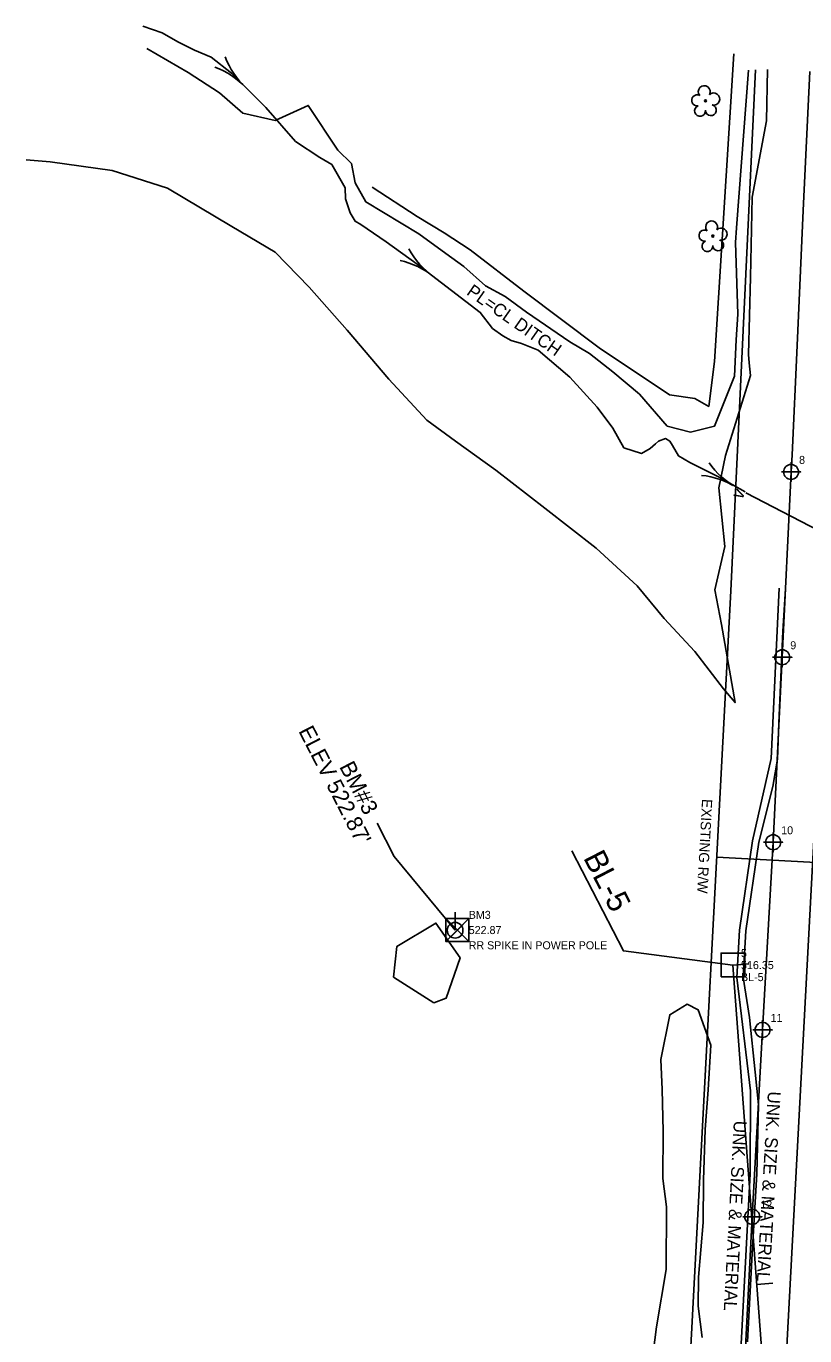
# Model space of a CAD drawing. Extents: x 1534145 to 1537876, y 509021 to 513201.
# Drawn here: x 1535793.4 to 1536036.7, y 512378.3 to 512787.3 of the extents above; entities that cross this region are included whole.
import ezdxf

# ---------------------------------------------------------------- set-up
doc = ezdxf.new("R2010")
doc.units = 0
for name, color, linetype in [('CTL Bench Mark CELL', 7, 'Continuous'), ('CTL Bench Mark Cogo Comment', 7, 'Continuous'), ('CTL Bench Mark Cogo Elevation', 7, 'Continuous'), ('CTL Bench Mark Cogo Number', 7, 'Continuous'), ('CTL Bench Mark Leader', 7, 'Continuous'), ('CTL Bench Mark Text', 7, 'Continuous'), ('CTL Supplemental Horizontal and Vertical CELL', 7, 'Continuous'), ('CTL Supplemental Horizontal and Vertical Cogo Comment', 7, 'Continuous'), ('CTL Supplemental Horizontal and Vertical Cogo Elevation', 7, 'Continuous'), ('CTL Supplemental Horizontal and Vertical Cogo Number', 7, 'Continuous'), ('Exist Horizontal Alignment', 7, 'Continuous'), ('Exist Horizontal Baseline Alignment', 7, 'Continuous'), ('Exist Horizontal Baseline Alignment Station Label', 7, 'Continuous'), ('Exist Horizontal Baseline Alignment Tick small', 7, 'Continuous'), ('Exist Hydro Stream Flow Arrow CELL', 7, 'Continuous'), ('Exist Hydro Stream or Body of Water', 7, 'Continuous'), ('Exist Other Culture Fence Line', 7, 'Continuous'), ('Exist Property Line Text', 7, 'Continuous'), ('Exist Right of Way Line', 7, 'Continuous'), ('Exist Right of Way Line Text', 7, 'Continuous'), ('Exist Right of Way Width CELL', 7, 'Continuous'), ('Exist Roads EOP', 7, 'Continuous'), ('Exist Roads EOP Cogo Number', 7, 'Continuous'), ('Exist Roads EOP Cogo Point CELL', 7, 'Continuous'), ('Exist Structure Minor Culvert Topo', 7, 'Continuous'), ('Exist Structure Minor Culvert Topo Terminator', 7, 'Continuous'), ('Exist Utilities Power Pole CELL', 7, 'Continuous'), ('Exist Utilities Telephone UG Cable', 7, 'Continuous'), ('Exist Utilities Telephone UG Cable Text', 7, 'Continuous'), ('Exist Utilities Telephone UG FO SUE', 7, 'Continuous'), ('Exist Utilities Telephone UG FO SUE Text', 7, 'Continuous'), ('Exist Vegetation Hedge Row', 7, 'Continuous'), ('Exist Vegetation Tree CELL', 7, 'Continuous'), ('Exist Vegetation Woods Line', 7, 'Continuous')]:
    doc.layers.add(name, color=color, linetype=linetype)

# ---------------------------------------------------------------- blocks, each defined once
blk = doc.blocks.new('EXIST UTILITIES POWER POLE')
at = {"layer": 'Exist Utilities Power Pole CELL'}
for q in [(0, 0.1125), (0, 0)]:
    blk.add_line((0, 0), q, dxfattribs=at)
blk.add_circle((0, 0), 0.049, dxfattribs=at)
blk = doc.blocks.new('CTL SUPPLEMENTAL HORIZONTAL AND VERTICAL')
at = {"layer": 'CTL Supplemental Horizontal and Vertical CELL'}
blk.add_line((0, 0), (0, 0), dxfattribs=at)
blk.add_lwpolyline([(-0.1043, 0.0004), (0.0005, 0.1052), (0.1055, 0.0002), (0.0007, -0.1047)], close=True, dxfattribs=at)
blk = doc.blocks.new('CTL BENCH MARK')
at = {"layer": 'CTL Bench Mark CELL'}
blk.add_line((0, 0), (0, 0), dxfattribs=at)
blk.add_lwpolyline([(-0.072, 0.07175), (0.07175, 0.07175), (0.07175, -0.072), (-0.072, -0.072)], close=True, dxfattribs=at)
for points in [[(0.07175, 0.07175), (-0.072, -0.072), (-0.000125, -0.000125), (0.07175, -0.072), (-0.072, 0.07175)], [(-0.000125, -0.000125), (0.07175, 0.07175), (-0.072, 0.07175), (-0.000125, -0.000125)], [(-0.000125, -0.000125), (-0.072, -0.072), (0.07175, -0.072), (-0.000125, -0.000125)]]:
    blk.add_lwpolyline(points, dxfattribs=at)

msp = doc.modelspace()

# ---------------------------------------------------------------- linework, layer by layer
at = {"layer": 'CTL Bench Mark Leader'}
msp.add_lwpolyline([(1535927.46, 512504.93), (1535908.43, 512527.94), (1535903.05, 512538.38)], dxfattribs=at)
at = {"layer": 'Exist Horizontal Alignment'}
msp.add_line((1536043.59, 512609.44), (1536025.64, 512271.8), dxfattribs=at)
at = {"layer": 'Exist Horizontal Baseline Alignment'}
msp.add_line((1536014.28, 512494.06), (1536066.28, 511797.6), dxfattribs=at)
at = {"layer": 'Exist Horizontal Baseline Alignment Station Label'}
msp.add_lwpolyline([(1535963.95, 512529.74), (1535980.06, 512498.5), (1536014.28, 512494.06)], dxfattribs=at)
at = {"layer": 'Exist Horizontal Baseline Alignment Tick small'}
for p, q in [((1536014.28, 512494.06), (1536019.27, 512494.43)), ((1536021.72, 512394.34), (1536026.71, 512394.71))]:
    msp.add_line(p, q, dxfattribs=at)
at = {"layer": 'Exist Hydro Stream Flow Arrow CELL'}
for p, q in [((1535857.53, 512772.63), (1535857.53, 512772.63)), ((1535915.6, 512712.96), (1535915.6, 512712.96)), ((1536009.95, 512646.45), (1536009.95, 512646.45))]:
    msp.add_line(p, q, dxfattribs=at)
for points in [[(1535855.58, 512777.77), (1535856.11, 512776.4), (1535856.8, 512775.07), (1535857.5, 512773.77), (1535858.28, 512772.55), (1535859.16, 512771.36), (1535860.1, 512770.2), (1535861.09, 512769.11)], [(1535852.37, 512774.52), (1535853.74, 512774), (1535855.08, 512773.33), (1535856.39, 512772.65), (1535857.61, 512771.88), (1535858.82, 512771.02), (1535859.99, 512770.09), (1535861.09, 512769.11)], [(1535912.99, 512717.8), (1535913.7, 512716.52), (1535914.56, 512715.29), (1535915.42, 512714.09), (1535916.36, 512712.99), (1535917.38, 512711.92), (1535918.47, 512710.89), (1535919.6, 512709.95)], [(1535910.24, 512714.15), (1535911.66, 512713.82), (1535913.08, 512713.33), (1535914.47, 512712.83), (1535915.79, 512712.23), (1535917.1, 512711.54), (1535918.38, 512710.77), (1535919.6, 512709.95)], [(1536006.81, 512650.96), (1536007.66, 512649.76), (1536008.65, 512648.64), (1536009.64, 512647.54), (1536010.7, 512646.56), (1536011.84, 512645.61), (1536013.04, 512644.71), (1536014.26, 512643.91)], [(1536004.48, 512647.01), (1536005.94, 512646.85), (1536007.4, 512646.53), (1536008.84, 512646.19), (1536010.22, 512645.74), (1536011.6, 512645.2), (1536012.96, 512644.58), (1536014.26, 512643.91)]]:
    msp.add_lwpolyline(points, dxfattribs=at)
at = {"layer": 'Exist Hydro Stream or Body of Water'}
msp.add_lwpolyline([(1536018.1, 512641.86), (1536009.95, 512646.45), (1536000.77, 512651.08), (1535997.2, 512653.11), (1535995.33, 512656.33), (1535994.53, 512657.73), (1535993.14, 512658.52), (1535991.04, 512657.67), (1535990.05, 512656.84), (1535988.35, 512655.38), (1535985.73, 512653.88), (1535980.22, 512655.65), (1535976.73, 512661.75), (1535971.8, 512668.31), (1535963.32, 512677.68), (1535953.37, 512686.16), (1535948.17, 512688.17), (1535945, 512689.2), (1535942.34, 512690.58), (1535939.15, 512692.86), (1535935.28, 512697.91), (1535926.3, 512704.82), (1535915.6, 512712.96), (1535905.92, 512719.99), (1535897.96, 512725.37), (1535896.22, 512726.4), (1535894.65, 512729.05), (1535893.17, 512733.35), (1535893.09, 512736.87), (1535891.02, 512740.47), (1535888.96, 512744.09), (1535885.13, 512746.3), (1535877.54, 512751.34), (1535868.26, 512761.96), (1535857.53, 512772.63), (1535851.19, 512777.67), (1535846.03, 512779.84), (1535840.84, 512782.43), (1535835.91, 512785.23), (1535829.84, 512787.32)], dxfattribs=at)
at = {"layer": 'Exist Other Culture Fence Line'}
msp.add_lwpolyline([(1535901.55, 512737.02), (1535915.61, 512727.91), (1535924.04, 512722.82), (1535932.11, 512717.42), (1535948.95, 512704.53), (1535972.5, 512686.87), (1535994.44, 512672.19), (1536002.33, 512671.02), (1536006.72, 512668.54), (1536008.5, 512682.58), (1536014.58, 512778.73)], dxfattribs=at)
at = {"layer": 'Exist Right of Way Line'}
for p, q in [((1536021.36, 512773.66), (1536013.63, 512610.95)), ((1536013.63, 512610.95), (1535995.68, 512273.4))]:
    msp.add_line(p, q, dxfattribs=at)
at = {"layer": 'Exist Right of Way Width CELL'}
msp.add_line((1536009.2, 512527.75), (1536052.92, 512525.42), dxfattribs=at)
at = {"layer": 'Exist Roads EOP'}
for points in [[(1536032.73, 512653.49), (1536034.33, 512687.61), (1536036.23, 512729.8), (1536038.31, 512773.15)], [(1536032.73, 512653.49), (1536032.43, 512648.1), (1536029.67, 512590.21), (1536026.84, 512532.42), (1536023.52, 512473.82), (1536020.32, 512415.44), (1536017.35, 512358.24), (1536017.13, 512355.26)]]:
    msp.add_lwpolyline(points, dxfattribs=at)
at = {"layer": 'Exist Roads EOP Cogo Point CELL'}
for points in [[(1536032.43, 512651.1), (1536032.43, 512645.1), (1536032.43, 512648.1), (1536035.43, 512648.1), (1536029.43, 512648.1)], [(1536029.67, 512593.21), (1536029.67, 512587.21), (1536029.67, 512590.21), (1536032.67, 512590.21), (1536026.67, 512590.21)], [(1536026.84, 512535.42), (1536026.84, 512529.42), (1536026.84, 512532.42), (1536029.84, 512532.42), (1536023.84, 512532.42)], [(1536023.52, 512476.82), (1536023.52, 512470.82), (1536023.52, 512473.82), (1536026.52, 512473.82), (1536020.52, 512473.82)], [(1536020.32, 512418.44), (1536020.32, 512412.44), (1536020.32, 512415.44), (1536023.32, 512415.44), (1536017.32, 512415.44)]]:
    msp.add_lwpolyline(points, dxfattribs=at)
for centre in [(1536032.43, 512648.1), (1536029.67, 512590.21), (1536026.84, 512532.42), (1536023.52, 512473.82), (1536020.32, 512415.44)]:
    msp.add_circle(centre, 2.34, dxfattribs=at)
at = {"layer": 'Exist Structure Minor Culvert Topo'}
msp.add_lwpolyline([(1536018.25, 512641.57), (1536072.53, 512613.43)], dxfattribs=at)
at = {"layer": 'Exist Utilities Telephone UG Cable'}
msp.add_lwpolyline([(1536028.72, 512611.84), (1536026.21, 512558.62), (1536020.37, 512532.89), (1536016.35, 512504.93), (1536015.43, 512490.16), (1536019.76, 512454.82), (1536019.68, 512428.91), (1536012.12, 512287.11), (1536007.46, 512205.21), (1536007.18, 512182.18), (1536007.51, 512112.19)], dxfattribs=at)
at = {"layer": 'Exist Utilities Telephone UG FO SUE'}
for p, q in [((1536030.72, 512611.71), (1536029.83, 512598.4)), ((1536029.83, 512598.4), (1536028.65, 512569.65)), ((1536028.65, 512569.65), (1536028.2, 512558.41)), ((1536028.2, 512558.41), (1536026.73, 512549.88)), ((1536026.73, 512549.88), (1536022.33, 512532.5)), ((1536022.33, 512532.5), (1536018.34, 512504.73)), ((1536018.34, 512504.73), (1536017.44, 512490.26)), ((1536017.44, 512490.26), (1536019.41, 512477.74)), ((1536019.41, 512477.74), (1536021.22, 512460.58)), ((1536021.22, 512460.58), (1536022.2, 512450.42)), ((1536022.2, 512450.42), (1536021.68, 512428.83)), ((1536021.68, 512428.83), (1536020.22, 512403.95)), ((1536020.22, 512403.95), (1536018.85, 512376.38))]:
    msp.add_line(p, q, dxfattribs=at)
at = {"layer": 'Exist Vegetation Hedge Row'}
msp.add_lwpolyline([(1535920.82, 512482.3), (1535908.16, 512490.31), (1535909.28, 512499.89), (1535921.44, 512507.19), (1535928.99, 512496.34), (1535924.65, 512483.72), (1535920.82, 512482.3)], dxfattribs=at)
at = {"layer": 'Exist Vegetation Tree CELL'}
for p, q in [((1536005.68, 512763.99), (1536005.68, 512763.99)), ((1536007.99, 512721.77), (1536007.99, 512721.77))]:
    msp.add_line(p, q, dxfattribs=at)
for centre in [(1536005.68, 512763.99), (1536007.99, 512721.77)]:
    msp.add_circle(centre, 0.326, dxfattribs=at)
for centre, radius, start, end in [((1536005.3, 512766.86), 1.86, 330.1651, 219.7134), ((1536003.08, 512764.15), 1.73, 62.6636, 279.3457), ((1536008.23, 512764.58), 1.9, 257.1011, 134.1999), ((1536003.98, 512760.87), 1.69, 111.5671, 6.231), ((1536007.36, 512761.09), 1.7, 181.2822, 74.56), ((1536007.6, 512724.64), 1.86, 330.1651, 219.7134), ((1536005.38, 512721.92), 1.73, 62.6636, 279.3457), ((1536010.54, 512722.36), 1.9, 257.1011, 134.1999), ((1536006.28, 512718.65), 1.69, 111.5671, 6.231), ((1536009.66, 512718.87), 1.7, 181.2822, 74.56)]:
    msp.add_arc(centre, radius, start, end, dxfattribs=at)
at = {"layer": 'Exist Vegetation Woods Line'}
for points in [[(1535831.08, 512780.4), (1535844, 512772.83), (1535853.83, 512766.49), (1535861.14, 512760.16), (1535871.19, 512757.9), (1535881.58, 512762.59), (1535890.83, 512748.57), (1535895.09, 512744.42), (1535896.27, 512738.37), (1535899.57, 512732.42), (1535916.15, 512722.43), (1535924.54, 512716.37), (1535930.2, 512712.22), (1535936.91, 512706.22), (1535943.1, 512702.9), (1535949.8, 512698.01), (1535963.31, 512688.73), (1535969.45, 512685.05), (1535976.69, 512679.41), (1535985.03, 512672.42), (1535993.74, 512662.44), (1536001.05, 512660.56), (1536008.51, 512662.41), (1536014.77, 512677.98), (1536015.25, 512689.33), (1536015.75, 512697.4), (1536015.06, 512719.76), (1536015.35, 512724.33), (1536019.14, 512773.55)], [(1536025.08, 512773.81), (1536024.74, 512757.76), (1536020.22, 512733.9), (1536019.74, 512708.9), (1536019.09, 512684.76), (1536019.32, 512682.14), (1536019.78, 512678.18), (1536011.95, 512653.25), (1536009.83, 512643.1), (1536011.76, 512624.78), (1536008.63, 512611.28), (1536010.67, 512600.43), (1536014.92, 512576.04), (1536011.29, 512580.31), (1536002.36, 512591.98), (1535992.75, 512602.37), (1535984.38, 512612.52), (1535971.52, 512624.27), (1535955.5, 512636.73), (1535940.18, 512648.63), (1535927.54, 512657.68), (1535918.6, 512664.26), (1535906.7, 512677.05), (1535893.77, 512692.42), (1535881.82, 512705.85), (1535871.2, 512716.79), (1535857.73, 512724.78), (1535837.57, 512736.77), (1535820.31, 512742.3), (1535800.9, 512745), (1535793.42, 512745.53)], [(1536004.61, 512377.71), (1536003.37, 512387.56), (1536003.49, 512396.6), (1536004.99, 512413.67), (1536005.1, 512426.91), (1536005.6, 512442.71), (1536006.5, 512455.13), (1536007.4, 512469.07), (1536003.41, 512480.12), (1535999.92, 512481.84), (1535994.51, 512478.54), (1535991.74, 512464.62), (1535992.18, 512455.19), (1535992.48, 512442.24), (1535992.34, 512427.38), (1535993.51, 512418.57), (1535993.39, 512398.99), (1535990.38, 512381.04), (1535989.37, 512372.96)]]:
    msp.add_lwpolyline(points, dxfattribs=at)

# ---------------------------------------------------------------- block references
at = {"layer": 'CTL Bench Mark CELL', "xscale": 50, "yscale": 50}
msp.add_blockref('CTL BENCH MARK', (1535928.2, 512505), dxfattribs=at)
at = {"layer": 'CTL Supplemental Horizontal and Vertical CELL', "xscale": 50, "yscale": 49.99999999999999, "rotation": 44.99999999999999}
msp.add_blockref('CTL SUPPLEMENTAL HORIZONTAL AND VERTICAL', (1536014.28, 512494.06), dxfattribs=at)
at = {"layer": 'Exist Utilities Power Pole CELL', "xscale": 50, "yscale": 50}
msp.add_blockref('EXIST UTILITIES POWER POLE', (1535927.46, 512504.93), dxfattribs=at)

# ---------------------------------------------------------------- texts
at = {"layer": 'CTL Bench Mark Cogo Comment'}
msp.add_text('RR SPIKE IN POWER POLE', height=2.5, dxfattribs=at).set_placement((1535931.7, 512499))
at = {"layer": 'CTL Bench Mark Cogo Elevation'}
msp.add_text('522.87', height=2.5, dxfattribs=at).set_placement((1535931.7, 512503.75))
at = {"layer": 'CTL Bench Mark Cogo Number'}
msp.add_text('BM3', height=2.5, dxfattribs=at).set_placement((1535931.7, 512508.5))
at = {"layer": 'CTL Bench Mark Text'}
for s, p in [("ELEV 522.87'", (1535878.38, 512567.19)), ('BM#3', (1535891.16, 512556.07))]:
    msp.add_text(s, height=5, rotation=297.2825, dxfattribs=at).set_placement(p)
at = {"layer": 'CTL Supplemental Horizontal and Vertical Cogo Comment'}
msp.add_text('BL-5', height=2.5, dxfattribs=at).set_placement((1536016.78, 512489.06))
at = {"layer": 'CTL Supplemental Horizontal and Vertical Cogo Elevation'}
msp.add_text('516.35', height=2.5, dxfattribs=at).set_placement((1536016.78, 512492.81))
at = {"layer": 'CTL Supplemental Horizontal and Vertical Cogo Number'}
msp.add_text('5', height=2.5, dxfattribs=at).set_placement((1536016.78, 512496.56))
at = {"layer": 'Exist Horizontal Baseline Alignment Station Label'}
msp.add_text('BL-5', height=7, rotation=297.2824, dxfattribs=at).set_placement((1535967.38, 512527.59))
at = {"layer": 'Exist Property Line Text'}
msp.add_text('PL=CL DITCH', height=4, rotation=325.0787, dxfattribs=at).set_placement((1535930.76, 512703.7))
at = {"layer": 'Exist Right of Way Line Text'}
msp.add_text('EXISTING R/W', height=3.2, rotation=266.9563, dxfattribs=at).set_placement((1536004.62, 512546))
at = {"layer": 'Exist Roads EOP Cogo Number'}
for s, p in [('8', (1536034.93, 512650.6)), ('9', (1536032.17, 512592.71)), ('10', (1536029.34, 512534.92)), ('11', (1536026.02, 512476.32)), ('12', (1536022.82, 512417.94))]:
    msp.add_text(s, height=2.5, dxfattribs=at).set_placement(p)
at = {"layer": 'Exist Structure Minor Culvert Topo Terminator'}
msp.add_text('v', height=4, rotation=62.3582, dxfattribs=at).set_placement((1536017.02, 512639.23))
at = {"layer": 'Exist Utilities Telephone UG Cable Text'}
msp.add_text('UNK. SIZE & MATERIAL', height=4, rotation=266.9468, dxfattribs=at).set_placement((1536014.56, 512445.54))
at = {"layer": 'Exist Utilities Telephone UG FO SUE Text'}
msp.add_text('UNK. SIZE & MATERIAL', height=4, rotation=266.6395, dxfattribs=at).set_placement((1536025.21, 512454.72))

doc.saveas('drawing.dxf')
